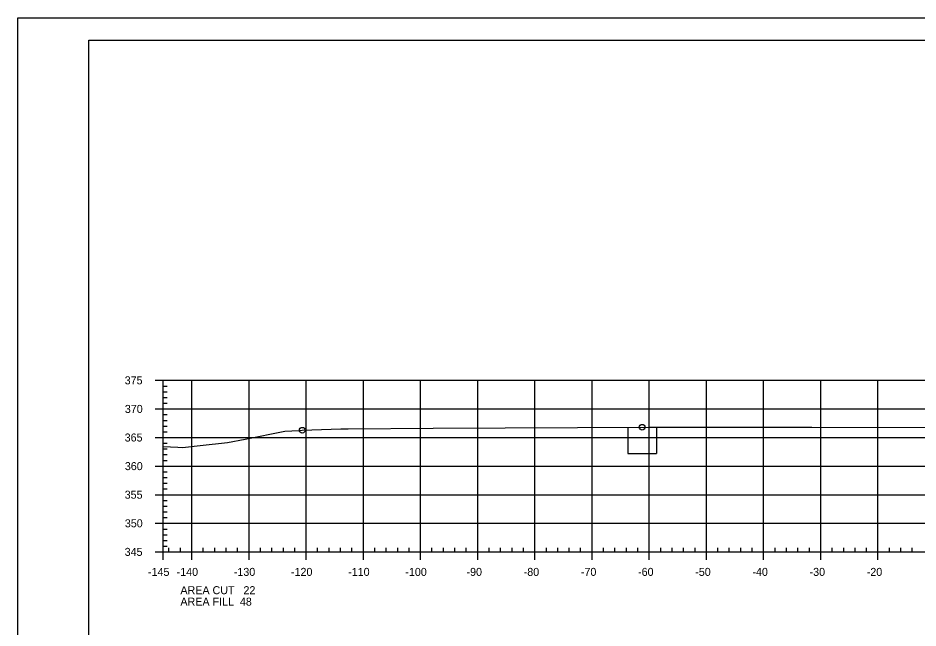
# Model space of a CAD drawing. Extents: x 1359801 to 1362404, y 372415 to 374228.
# Drawn here: x 1359800.9 to 1359958.4, y 372841.3 to 372947.9 of the extents above; entities that cross this region are included whole.
import ezdxf

# ---------------------------------------------------------------- set-up
doc = ezdxf.new("R2010")
doc.units = 0
for name, color, linetype in [('S_DRG_PT_SYM', 7, 'Continuous'), ('S_MAILBOX', 7, 'Continuous'), ('S_PRIMARY_CTL', 7, 'Continuous'), ('S_SHOULDER', 7, 'Continuous'), ('S_UTILITY_POLE_ANNOT', 7, 'Continuous'), ('S_UTL_PT_SYM', 7, 'Continuous'), ('S_WATER_UTILITIES', 7, 'Continuous')]:
    doc.layers.add(name, color=color, linetype=linetype)

msp = doc.modelspace()

# ---------------------------------------------------------------- linework, layer by layer
at = {"layer": 'S_DRG_PT_SYM'}
msp.add_lwpolyline([(1359826.35, 372873.03), (1359828.88, 372872.89), (1359829.66, 372872.84), (1359830.25, 372872.92), (1359832.78, 372873.18), (1359837.61, 372873.69), (1359840.68, 372874.3), (1359847.59, 372875.68), (1359850.05, 372875.82), (1359850.66, 372875.85), (1359857.43, 372876.07), (1359858.67, 372876.11), (1359873.56, 372876.2), (1359911.37, 372876.38), (1359939.76, 372876.36), (1359961.54, 372876.35)], dxfattribs=at)
at = {"layer": 'S_MAILBOX'}
for p, q in [((1359826.35, 372884.58), (1360116.35, 372884.58)), ((1359826.35, 372854.58), (1359826.35, 372884.58)), ((1359826.35, 372884.58), (1360116.35, 372884.58)), ((1359826.35, 372854.58), (1359826.35, 372884.58)), ((1359831.35, 372854.58), (1359831.35, 372884.58)), ((1359831.35, 372854.58), (1359831.35, 372884.58)), ((1359841.35, 372854.58), (1359841.35, 372884.58)), ((1359841.35, 372854.58), (1359841.35, 372884.58)), ((1359851.35, 372854.58), (1359851.35, 372884.58)), ((1359851.35, 372854.58), (1359851.35, 372884.58)), ((1359861.35, 372854.58), (1359861.35, 372884.58)), ((1359861.35, 372854.58), (1359861.35, 372884.58)), ((1359871.35, 372854.58), (1359871.35, 372884.58)), ((1359871.35, 372854.58), (1359871.35, 372884.58)), ((1359881.35, 372854.58), (1359881.35, 372884.58)), ((1359881.35, 372854.58), (1359881.35, 372884.58)), ((1359891.35, 372854.58), (1359891.35, 372884.58)), ((1359891.35, 372854.58), (1359891.35, 372884.58)), ((1359901.35, 372854.58), (1359901.35, 372884.58)), ((1359901.35, 372854.58), (1359901.35, 372884.58)), ((1359911.35, 372854.58), (1359911.35, 372884.58)), ((1359911.35, 372854.58), (1359911.35, 372884.58)), ((1359921.35, 372854.58), (1359921.35, 372884.58)), ((1359921.35, 372854.58), (1359921.35, 372884.58)), ((1359931.35, 372854.58), (1359931.35, 372884.58)), ((1359931.35, 372854.58), (1359931.35, 372884.58)), ((1359941.35, 372854.58), (1359941.35, 372884.58)), ((1359941.35, 372854.58), (1359941.35, 372884.58)), ((1359951.35, 372854.58), (1359951.35, 372884.58)), ((1359951.35, 372854.58), (1359951.35, 372884.58)), ((1359826.35, 372879.58), (1360116.35, 372879.58)), ((1359826.35, 372879.58), (1360116.35, 372879.58)), ((1359826.35, 372874.58), (1360116.35, 372874.58)), ((1359826.35, 372874.58), (1360116.35, 372874.58)), ((1359826.35, 372869.58), (1360116.35, 372869.58)), ((1359826.35, 372869.58), (1360116.35, 372869.58)), ((1359826.35, 372864.58), (1360116.35, 372864.58)), ((1359826.35, 372864.58), (1360116.35, 372864.58)), ((1359826.35, 372859.58), (1360116.35, 372859.58)), ((1359826.35, 372859.58), (1360116.35, 372859.58)), ((1359826.35, 372854.58), (1360116.35, 372854.58)), ((1359826.35, 372854.58), (1360116.35, 372854.58))]:
    msp.add_line(p, q, dxfattribs=at)
at = {"layer": 'S_SHOULDER'}
msp.add_line((1359800.95, 372947.94), (1360134.28, 372947.94), dxfattribs=at)
for points in [[(1359800.94, 372947.94), (1360134.28, 372947.94), (1360134.28, 372734.6), (1359800.94, 372734.6)], [(1360047.27, 372944.04), (1360047.27, 372934.16), (1360083, 372934.16), (1360083, 372931.24), (1360106.2, 372931.24), (1360106.2, 372906.91), (1360129.53, 372906.91), (1360129.53, 372738.58), (1359813.35, 372738.58), (1359813.35, 372944.04)]]:
    msp.add_lwpolyline(points, close=True, dxfattribs=at)
for centre in [(1359850.66, 372875.85), (1359910.11, 372876.38)]:
    msp.add_circle(centre, 0.5, dxfattribs=at)
at = {"layer": 'S_UTILITY_POLE_ANNOT'}
for p, q in [((1359907.59, 372876.38), (1359907.59, 372871.8)), ((1359912.59, 372876.38), (1359912.59, 372871.8)), ((1359907.59, 372871.8), (1359912.59, 372871.8))]:
    msp.add_line(p, q, dxfattribs=at)
at = {"layer": 'S_UTL_PT_SYM'}
for p, q in [((1359813.35, 372944.04), (1360129.53, 372944.04)), ((1359813.35, 372738.58), (1359813.35, 372944.04))]:
    msp.add_line(p, q, dxfattribs=at)
at = {"layer": 'S_WATER_UTILITIES'}
for p, q in [((1359824.95, 372884.58), (1359826.35, 372884.58)), ((1359826.35, 372854.58), (1359826.35, 372884.58)), ((1359826.35, 372883.58), (1359827.05, 372883.58)), ((1359826.35, 372882.58), (1359827.05, 372882.58)), ((1359826.35, 372881.58), (1359827.05, 372881.58)), ((1359824.95, 372879.58), (1359826.35, 372879.58)), ((1359826.35, 372880.58), (1359827.05, 372880.58)), ((1359826.35, 372878.58), (1359827.05, 372878.58)), ((1359826.35, 372877.58), (1359827.05, 372877.58)), ((1359826.35, 372876.58), (1359827.05, 372876.58)), ((1359826.35, 372875.58), (1359827.05, 372875.58)), ((1359824.95, 372874.58), (1359826.35, 372874.58)), ((1359826.35, 372873.58), (1359827.05, 372873.58)), ((1359826.35, 372872.58), (1359827.05, 372872.58)), ((1359826.35, 372871.58), (1359827.05, 372871.58)), ((1359826.35, 372870.58), (1359827.05, 372870.58)), ((1359824.95, 372869.58), (1359826.35, 372869.58)), ((1359826.35, 372868.58), (1359827.05, 372868.58)), ((1359826.35, 372867.58), (1359827.05, 372867.58)), ((1359826.35, 372866.58), (1359827.05, 372866.58)), ((1359826.35, 372865.58), (1359827.05, 372865.58)), ((1359824.95, 372864.58), (1359826.35, 372864.58)), ((1359826.35, 372863.58), (1359827.05, 372863.58)), ((1359826.35, 372862.58), (1359827.05, 372862.58)), ((1359826.35, 372861.58), (1359827.05, 372861.58)), ((1359826.35, 372860.58), (1359827.05, 372860.58)), ((1359824.95, 372859.58), (1359826.35, 372859.58)), ((1359826.35, 372858.58), (1359827.05, 372858.58)), ((1359826.35, 372857.58), (1359827.05, 372857.58)), ((1359826.35, 372856.58), (1359827.05, 372856.58)), ((1359824.95, 372854.58), (1359826.35, 372854.58)), ((1359826.35, 372855.58), (1359827.05, 372855.58)), ((1359826.35, 372854.58), (1359826.35, 372855.28)), ((1359826.35, 372854.58), (1360116.35, 372854.58)), ((1359826.35, 372853.18), (1359826.35, 372854.58)), ((1359827.35, 372854.58), (1359827.35, 372855.28)), ((1359829.35, 372854.58), (1359829.35, 372855.28)), ((1359831.35, 372853.18), (1359831.35, 372854.58)), ((1359833.35, 372854.58), (1359833.35, 372855.28)), ((1359835.35, 372854.58), (1359835.35, 372855.28)), ((1359837.35, 372854.58), (1359837.35, 372855.28)), ((1359839.35, 372854.58), (1359839.35, 372855.28)), ((1359841.35, 372853.18), (1359841.35, 372854.58)), ((1359843.35, 372854.58), (1359843.35, 372855.28)), ((1359845.35, 372854.58), (1359845.35, 372855.28)), ((1359847.35, 372854.58), (1359847.35, 372855.28)), ((1359849.35, 372854.58), (1359849.35, 372855.28)), ((1359851.35, 372853.18), (1359851.35, 372854.58)), ((1359853.35, 372854.58), (1359853.35, 372855.28)), ((1359855.35, 372854.58), (1359855.35, 372855.28)), ((1359857.35, 372854.58), (1359857.35, 372855.28)), ((1359859.35, 372854.58), (1359859.35, 372855.28)), ((1359861.35, 372853.18), (1359861.35, 372854.58)), ((1359863.35, 372854.58), (1359863.35, 372855.28)), ((1359865.35, 372854.58), (1359865.35, 372855.28)), ((1359867.35, 372854.58), (1359867.35, 372855.28)), ((1359869.35, 372854.58), (1359869.35, 372855.28)), ((1359871.35, 372853.18), (1359871.35, 372854.58)), ((1359873.35, 372854.58), (1359873.35, 372855.28)), ((1359875.35, 372854.58), (1359875.35, 372855.28)), ((1359877.35, 372854.58), (1359877.35, 372855.28)), ((1359879.35, 372854.58), (1359879.35, 372855.28)), ((1359881.35, 372853.18), (1359881.35, 372854.58)), ((1359883.35, 372854.58), (1359883.35, 372855.28)), ((1359885.35, 372854.58), (1359885.35, 372855.28)), ((1359887.35, 372854.58), (1359887.35, 372855.28)), ((1359889.35, 372854.58), (1359889.35, 372855.28)), ((1359891.35, 372853.18), (1359891.35, 372854.58)), ((1359893.35, 372854.58), (1359893.35, 372855.28)), ((1359895.35, 372854.58), (1359895.35, 372855.28)), ((1359897.35, 372854.58), (1359897.35, 372855.28)), ((1359899.35, 372854.58), (1359899.35, 372855.28)), ((1359901.35, 372853.18), (1359901.35, 372854.58)), ((1359903.35, 372854.58), (1359903.35, 372855.28)), ((1359905.35, 372854.58), (1359905.35, 372855.28)), ((1359907.35, 372854.58), (1359907.35, 372855.28)), ((1359909.35, 372854.58), (1359909.35, 372855.28)), ((1359911.35, 372853.18), (1359911.35, 372854.58)), ((1359913.35, 372854.58), (1359913.35, 372855.28)), ((1359915.35, 372854.58), (1359915.35, 372855.28)), ((1359917.35, 372854.58), (1359917.35, 372855.28)), ((1359919.35, 372854.58), (1359919.35, 372855.28)), ((1359921.35, 372853.18), (1359921.35, 372854.58)), ((1359923.35, 372854.58), (1359923.35, 372855.28)), ((1359925.35, 372854.58), (1359925.35, 372855.28)), ((1359927.35, 372854.58), (1359927.35, 372855.28)), ((1359929.35, 372854.58), (1359929.35, 372855.28)), ((1359931.35, 372853.18), (1359931.35, 372854.58)), ((1359933.35, 372854.58), (1359933.35, 372855.28)), ((1359935.35, 372854.58), (1359935.35, 372855.28)), ((1359937.35, 372854.58), (1359937.35, 372855.28)), ((1359939.35, 372854.58), (1359939.35, 372855.28)), ((1359941.35, 372853.18), (1359941.35, 372854.58)), ((1359943.35, 372854.58), (1359943.35, 372855.28)), ((1359945.35, 372854.58), (1359945.35, 372855.28)), ((1359947.35, 372854.58), (1359947.35, 372855.28)), ((1359949.35, 372854.58), (1359949.35, 372855.28)), ((1359951.35, 372853.18), (1359951.35, 372854.58)), ((1359953.35, 372854.58), (1359953.35, 372855.28)), ((1359955.35, 372854.58), (1359955.35, 372855.28)), ((1359957.35, 372854.58), (1359957.35, 372855.28))]:
    msp.add_line(p, q, dxfattribs=at)

# ---------------------------------------------------------------- texts
at = {"layer": 'S_PRIMARY_CTL'}
for s, p in [('375', (1359819.6, 372883.88)), ('370', (1359819.63, 372878.88)), ('365', (1359819.6, 372873.88)), ('360', (1359819.63, 372868.88)), ('355', (1359819.6, 372863.88)), ('350', (1359819.63, 372858.88)), ('345', (1359819.6, 372853.88)), ('-145', (1359823.68, 372850.38)), ('-140', (1359828.69, 372850.38)), ('-130', (1359838.69, 372850.38)), ('-120', (1359848.69, 372850.38)), ('-110', (1359858.69, 372850.38)), ('-100', (1359868.69, 372850.38)), ('-90', (1359879.39, 372850.38)), ('-80', (1359889.39, 372850.38)), ('-70', (1359899.39, 372850.38)), ('-60', (1359909.39, 372850.38)), ('-50', (1359919.39, 372850.38)), ('-40', (1359929.39, 372850.38)), ('-30', (1359939.39, 372850.38)), ('-20', (1359949.39, 372850.38)), ('AREA CUT   22', (1359829.35, 372847.18)), ('AREA FILL  48', (1359829.35, 372845.18))]:
    msp.add_text(s, height=1.4, dxfattribs=at).set_placement(p)
at = {"layer": 'S_SHOULDER'}
msp.add_text('+', height=0.1, dxfattribs=at).set_placement((1359858.62, 372876.06))

doc.saveas('drawing.dxf')
